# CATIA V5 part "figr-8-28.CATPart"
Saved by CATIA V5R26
Part number: Part1
Bounding box of the stored display mesh (mm): x 37.5 to 207.5, y 10 to 85, z 0 to 113
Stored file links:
  D:\_Deepak\CATIA\CATIA V5-6R2016_Deepak\Resources\Part files\Partfiles\c08_catia_v5_6r2016_prt\figr-8-28.CATPart
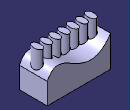
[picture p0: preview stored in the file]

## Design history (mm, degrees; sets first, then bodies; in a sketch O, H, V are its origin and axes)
Set1
  Plane1: type Offset, RefPlane xy-plane, Offset 113
Body1 (main body)
  Sketch1 on xy-plane, origin (0, 0, 0), H (1, 0, 0), V (0, 1, 0)
    line L1 (-37.5, 85) -> (37.5, 85)
    line L2 (37.5, 85) -> (37.5, -85)
    line L3 (37.5, -85) -> (-37.5, -85)
    line L4 (-37.5, -85) -> (-37.5, 85)
    axis line L5 (37.5, -85) -> (-37.5, 85)
    length L3 = 75
    length L2 = 170
    horizontal: L1 H, L3 H
    vertical: L2 V, L4 V
    midpoint: O L5
  Pad1: profile Sketch1, direction (0, 0, 1), length 83
  Sketch2 on face of Pad1, origin (37.5, 0, 0), H (0, 1, 0), V (0, 0, 1)
    spline S1 through (-85, 56.7422) (-58.5369, 80.0687) (-27.7952, 70.201) (85, 83)
    reference projected line E1 (85, 0) -> (85, 83) from edge [face of Pad1 | face of Pad1]
    reference projected line E2 (-85, 0) -> (-85, 83) from edge [face of Pad1 | face of Pad1]
    reference projected line E3 (-85, 83) -> (85, 83) from edge [face of Pad1 | face of Pad1]
    point P1 (85, 83)
    point P3 (-85, 56.7422)
    coincidence: P1 E1, P3 E2, P1 E3
  Pocket1: profile Sketch2, direction (-1, 0, 0), length 83
  Rotate1: ToTransfor Pocket1, Axis edge [face of Pad1 | face of Pad1], Angle 90
  Sketch3 on Plane1, origin (0, 0, 113), H (1, 0, 0), V (0, 1, 0)
    ellipse A1 centre (195.4286, 45.9861) semi-axes 14.9247, 8.8005 rotation 90
  Pad2: profile Sketch3, direction (0, 0, -1), up to face of Pocket1
  RectPattern1: of Pad2, direction 1 instances 7, spacing 24, along edge [face of Pad1 | face of Pad1]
